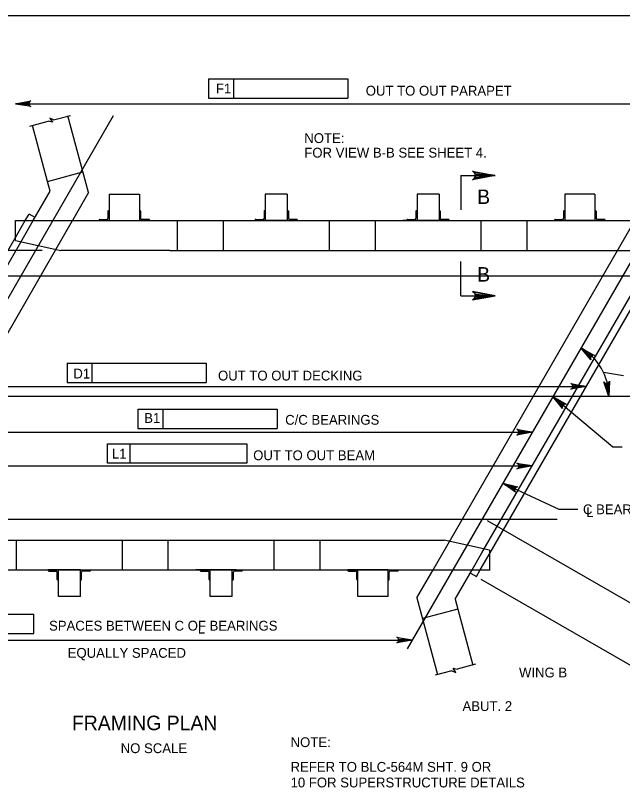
# Model space of a CAD drawing. Extents: x 638175 to 640495, y 294277 to 298435.
# Drawn here: x 638659.6 to 638845, y 295214.5 to 295450.5 of the extents above; entities that cross this region are included whole.
import ezdxf

# ---------------------------------------------------------------- set-up
doc = ezdxf.new("R2010")
doc.units = 0
for name, color, linetype in [('2', 7, 'Continuous'), ('3', 7, 'Continuous'), ('4', 7, 'Continuous')]:
    doc.layers.add(name, color=color, linetype=linetype)

msp = doc.modelspace()

# ---------------------------------------------------------------- linework, layer by layer
at = {"layer": '2'}
for p, q in [((638475.46, 295450.46), (639261.46, 295450.46)), ((638681.87, 295396.3), (638675.59, 295419.73)), ((638669.38, 295399.76), (638664.8, 295416.84)), ((638669.38, 295399.76), (638680.17, 295402.65)), ((638670.19, 295396.73), (638669.38, 295399.76)), ((638795.64, 295401.55), (638795.64, 295391.07)), ((638795.64, 295401.55), (638806.12, 295401.55)), ((638665, 295387.76), (638670.19, 295396.73)), ((638681.87, 295396.3), (638676.94, 295387.76)), ((638688.19, 295395.84), (638697.43, 295395.84)), ((638688.19, 295395.84), (638688.19, 295387.75)), ((638697.43, 295395.84), (638697.43, 295387.75)), ((638742.58, 295395.84), (638735.85, 295395.84)), ((638742.58, 295395.84), (638735.85, 295395.84)), ((638735.85, 295395.84), (638735.85, 295387.75)), ((638742.58, 295395.84), (638742.58, 295387.75)), ((638788.95, 295395.84), (638782.22, 295395.84)), ((638788.95, 295395.84), (638782.22, 295395.84)), ((638788.95, 295395.84), (638782.22, 295395.84)), ((638782.22, 295395.84), (638782.22, 295387.75)), ((638788.95, 295395.84), (638788.95, 295387.75)), ((638836.56, 295395.84), (638827.33, 295395.84)), ((638827.33, 295395.84), (638827.33, 295387.75)), ((638836.56, 295395.84), (638836.56, 295387.75)), ((638687.83, 295390.66), (638687.83, 295388.48)), ((638688.01, 295390.84), (638688.19, 295390.84)), ((638688.19, 295390.84), (638688.19, 295387.75)), ((638697.61, 295390.84), (638697.43, 295390.84)), ((638697.43, 295390.84), (638697.43, 295387.75)), ((638697.79, 295390.66), (638697.79, 295388.48)), ((638735.49, 295390.66), (638735.49, 295388.48)), ((638735.67, 295390.84), (638735.85, 295390.84)), ((638735.85, 295390.84), (638735.85, 295387.75)), ((638742.76, 295390.84), (638742.58, 295390.84)), ((638742.58, 295390.84), (638742.58, 295387.75)), ((638742.95, 295390.66), (638742.95, 295388.48)), ((638781.85, 295390.66), (638781.85, 295388.48)), ((638782.04, 295390.84), (638782.22, 295390.84)), ((638782.22, 295390.84), (638782.22, 295387.75)), ((638789.13, 295390.84), (638788.95, 295390.84)), ((638788.95, 295390.84), (638788.95, 295387.75)), ((638789.31, 295390.66), (638789.31, 295388.48)), ((638826.96, 295390.66), (638826.96, 295388.48)), ((638827.15, 295390.84), (638827.33, 295390.84)), ((638827.33, 295390.84), (638827.33, 295387.75)), ((638836.75, 295390.84), (638836.56, 295390.84)), ((638836.56, 295390.84), (638836.56, 295387.75)), ((638836.93, 295390.66), (638836.93, 295388.48)), ((638615.32, 295281.03), (638676.94, 295387.76)), ((638659.57, 295387.75), (638863.14, 295387.75)), ((638659.57, 295382.59), (638662.55, 295387.75)), ((638659.57, 295381.72), (638659.57, 295387.75)), ((638662.02, 295382.59), (638665, 295387.76)), ((638662.55, 295387.75), (638663.71, 295389.77)), ((638665.56, 295388.71), (638663.71, 295389.77)), ((638665, 295387.76), (638860.69, 295387.76)), ((638685.1, 295387.94), (638685.1, 295387.75)), ((638688.19, 295387.75), (638685.1, 295387.75)), ((638685.28, 295388.12), (638687.46, 295388.12)), ((638688.19, 295387.75), (638697.43, 295387.75)), ((638697.43, 295387.75), (638700.52, 295387.75)), ((638700.34, 295388.12), (638698.15, 295388.12)), ((638700.52, 295387.94), (638700.52, 295387.75)), ((638708.98, 295387.75), (638708.98, 295378.63)), ((638723.05, 295387.75), (638723.05, 295378.63)), ((638732.76, 295387.94), (638732.76, 295387.75)), ((638735.85, 295387.75), (638732.76, 295387.75)), ((638732.95, 295388.12), (638735.13, 295388.12)), ((638742.58, 295387.75), (638735.85, 295387.75)), ((638742.58, 295387.75), (638735.85, 295387.75)), ((638742.58, 295387.75), (638745.67, 295387.75)), ((638745.49, 295388.12), (638743.31, 295388.12)), ((638745.67, 295387.94), (638745.67, 295387.75)), ((638755.39, 295387.75), (638755.39, 295378.63)), ((638769.41, 295387.75), (638769.41, 295378.63)), ((638780.96, 295387.75), (638777.87, 295387.75)), ((638779.13, 295387.94), (638779.13, 295387.75)), ((638782.22, 295387.75), (638779.13, 295387.75)), ((638779.31, 295388.12), (638781.49, 295388.12)), ((638790.2, 295387.75), (638780.96, 295387.75)), ((638788.95, 295387.75), (638782.22, 295387.75)), ((638788.95, 295387.75), (638782.22, 295387.75)), ((638787.14, 295281.03), (638848.76, 295387.76)), ((638788.95, 295387.75), (638792.04, 295387.75)), ((638791.85, 295388.12), (638789.67, 295388.12)), ((638790.2, 295387.75), (638793.29, 295387.75)), ((638792.04, 295387.94), (638792.04, 295387.75)), ((638801.75, 295387.75), (638801.75, 295378.63)), ((638815.78, 295387.75), (638815.78, 295378.63)), ((638824.24, 295387.94), (638824.24, 295387.75)), ((638827.33, 295387.75), (638824.24, 295387.75)), ((638824.42, 295388.12), (638826.6, 295388.12)), ((638836.56, 295387.75), (638827.33, 295387.75)), ((638836.56, 295387.75), (638839.65, 295387.75)), ((638839.47, 295388.12), (638837.29, 295388.12)), ((638839.65, 295387.94), (638839.65, 295387.75)), ((638604.93, 295287.95), (638659.57, 295382.59)), ((638606.97, 295287.25), (638662.02, 295382.59)), ((638659.57, 295381.72), (638673.41, 295378.63)), ((638802.05, 295286.2), (638857.1, 295381.54)), ((638804.51, 295286.2), (638859.56, 295381.54)), ((638706.72, 295378.63), (638673.41, 295378.63)), ((638706.72, 295378.63), (638849.29, 295378.63)), ((638795.64, 295364.82), (638795.64, 295375.31)), ((638795.64, 295364.82), (638806.12, 295364.82)), ((638648.08, 295290.15), (638790.52, 295290.15)), ((638659.88, 295281.03), (638659.88, 295290.15)), ((638692.22, 295281.03), (638692.22, 295290.15)), ((638706.24, 295281.03), (638706.24, 295290.15)), ((638738.58, 295281.03), (638738.58, 295290.15)), ((638752.61, 295281.03), (638752.61, 295290.15)), ((638804.39, 295287.05), (638790.52, 295290.15)), ((638799.07, 295281.03), (638802.05, 295286.2)), ((638801.53, 295281.03), (638804.51, 295286.2)), ((638804.39, 295287.05), (638804.39, 295281.03)), ((638600.93, 295281.03), (638804.51, 295281.03)), ((638600.93, 295281.03), (638799.6, 295281.03)), ((638603.38, 295281.03), (638802.05, 295281.03)), ((638669.59, 295280.84), (638669.59, 295281.03)), ((638672.69, 295281.03), (638669.59, 295281.03)), ((638669.78, 295280.66), (638671.96, 295280.66)), ((638672.32, 295278.12), (638672.32, 295280.3)), ((638679.41, 295281.03), (638672.69, 295281.03)), ((638679.41, 295281.03), (638672.69, 295281.03)), ((638672.69, 295277.94), (638672.69, 295281.03)), ((638672.69, 295272.94), (638672.69, 295281.03)), ((638679.41, 295281.03), (638682.5, 295281.03)), ((638679.41, 295277.94), (638679.41, 295281.03)), ((638679.41, 295272.94), (638679.41, 295281.03)), ((638679.78, 295278.12), (638679.78, 295280.3)), ((638682.32, 295280.66), (638680.14, 295280.66)), ((638682.5, 295280.84), (638682.5, 295281.03)), ((638717.79, 295281.03), (638714.7, 295281.03)), ((638715.96, 295280.84), (638715.96, 295281.03)), ((638719.05, 295281.03), (638715.96, 295281.03)), ((638716.14, 295280.66), (638718.32, 295280.66)), ((638727.03, 295281.03), (638717.79, 295281.03)), ((638718.69, 295278.12), (638718.69, 295280.3)), ((638725.78, 295281.03), (638719.05, 295281.03)), ((638725.78, 295281.03), (638719.05, 295281.03)), ((638719.05, 295277.94), (638719.05, 295281.03)), ((638719.05, 295272.94), (638719.05, 295281.03)), ((638725.78, 295281.03), (638728.87, 295281.03)), ((638725.78, 295277.94), (638725.78, 295281.03)), ((638725.78, 295272.94), (638725.78, 295281.03)), ((638726.14, 295278.12), (638726.14, 295280.3)), ((638728.69, 295280.66), (638726.5, 295280.66)), ((638727.03, 295281.03), (638730.12, 295281.03)), ((638728.87, 295280.84), (638728.87, 295281.03)), ((638761.07, 295280.84), (638761.07, 295281.03)), ((638764.16, 295281.03), (638761.07, 295281.03)), ((638761.25, 295280.66), (638763.43, 295280.66)), ((638763.79, 295278.12), (638763.79, 295280.3)), ((638773.39, 295281.03), (638764.16, 295281.03)), ((638764.16, 295272.94), (638764.16, 295281.03)), ((638764.16, 295277.94), (638764.16, 295281.03)), ((638773.39, 295281.03), (638776.49, 295281.03)), ((638773.39, 295272.94), (638773.39, 295281.03)), ((638773.39, 295277.94), (638773.39, 295281.03)), ((638773.76, 295278.12), (638773.76, 295280.3)), ((638776.3, 295280.66), (638774.12, 295280.66)), ((638776.49, 295280.84), (638776.49, 295281.03)), ((638782.2, 295272.48), (638787.14, 295281.03)), ((638793.89, 295272.05), (638799.07, 295281.03)), ((638798.52, 295280.07), (638800.36, 295279.01)), ((638800.36, 295279.01), (638801.53, 295281.03)), ((638672.5, 295277.94), (638672.69, 295277.94)), ((638679.59, 295277.94), (638679.41, 295277.94)), ((638718.87, 295277.94), (638719.05, 295277.94)), ((638725.96, 295277.94), (638725.78, 295277.94)), ((638763.98, 295277.94), (638764.16, 295277.94)), ((638773.58, 295277.94), (638773.39, 295277.94)), ((638679.41, 295272.94), (638672.69, 295272.94)), ((638679.41, 295272.94), (638672.69, 295272.94)), ((638725.78, 295272.94), (638719.05, 295272.94)), ((638725.78, 295272.94), (638719.05, 295272.94)), ((638725.78, 295272.94), (638719.05, 295272.94)), ((638773.39, 295272.94), (638764.16, 295272.94)), ((638782.2, 295272.48), (638788.48, 295249.06)), ((638793.89, 295272.05), (638794.7, 295269.03)), ((638638.68, 295267.51), (638665.18, 295267.51)), ((638665.18, 295261.6), (638665.18, 295267.51)), ((638794.7, 295269.03), (638783.91, 295266.13)), ((638794.7, 295269.03), (638799.27, 295251.95)), ((638638.67, 295261.6), (638665.18, 295261.6))]:
    msp.add_line(p, q, dxfattribs=at)
for points in [[(638806.12, 295401.55), (638799.13, 295400.24), (638799.67, 295400.62), (638799.95, 295401.08), (638800.03, 295401.55), (638799.95, 295402.02), (638799.67, 295402.49), (638799.13, 295402.86), (638806.12, 295401.55), (638799.67, 295402.49), (638799.95, 295402.02), (638806.12, 295401.55), (638800.03, 295401.55), (638799.95, 295401.08), (638806.12, 295401.55), (638799.67, 295400.62)], [(638806.12, 295364.82), (638799.13, 295366.13), (638799.67, 295365.76), (638799.95, 295365.29), (638800.03, 295364.82), (638799.95, 295364.35), (638799.67, 295363.89), (638799.13, 295363.51), (638806.12, 295364.82), (638799.67, 295363.89), (638799.95, 295364.35), (638806.12, 295364.82), (638800.03, 295364.82), (638799.95, 295365.29), (638806.12, 295364.82), (638799.67, 295365.76)]]:
    msp.add_lwpolyline(points, dxfattribs=at)
for centre, radius, start, end in [((638688.01, 295390.66), 0.182, 90, 179.9984), ((638697.61, 295390.66), 0.182, 0.0016, 90), ((638735.67, 295390.66), 0.182, 90, 179.9984), ((638742.76, 295390.66), 0.182, 0.0016, 90), ((638782.04, 295390.66), 0.182, 90, 179.9984), ((638789.13, 295390.66), 0.182, 0.0016, 90), ((638827.15, 295390.66), 0.182, 90, 179.9984), ((638836.75, 295390.66), 0.182, 0.0016, 90), ((638685.28, 295387.94), 0.182, 90, 179.9984), ((638687.46, 295388.48), 0.364, 270, 359.9984), ((638698.15, 295388.48), 0.364, 180.0016, 270), ((638700.34, 295387.94), 0.182, 0.0016, 90), ((638732.95, 295387.94), 0.182, 90, 179.9984), ((638735.13, 295388.48), 0.364, 270, 359.9984), ((638743.31, 295388.48), 0.364, 180.0016, 270), ((638745.49, 295387.94), 0.182, 0.0016, 90), ((638779.31, 295387.94), 0.182, 90, 179.9984), ((638781.49, 295388.48), 0.364, 270, 359.9984), ((638789.67, 295388.48), 0.364, 180.0016, 270), ((638791.85, 295387.94), 0.182, 0.0016, 90), ((638824.42, 295387.94), 0.182, 90, 179.9984), ((638826.6, 295388.48), 0.364, 270, 359.9984), ((638837.29, 295388.48), 0.364, 180.0016, 270), ((638839.47, 295387.94), 0.182, 0.0016, 90), ((638669.78, 295280.84), 0.182, 180.0016, 270), ((638671.96, 295280.3), 0.364, 0.0016, 90), ((638680.14, 295280.3), 0.364, 90, 179.9984), ((638682.32, 295280.84), 0.182, 270, 359.9984), ((638716.14, 295280.84), 0.182, 180.0016, 270), ((638718.32, 295280.3), 0.364, 0.0016, 90), ((638726.5, 295280.3), 0.364, 90, 179.9984), ((638728.69, 295280.84), 0.182, 270, 359.9984), ((638761.25, 295280.84), 0.182, 180.0016, 270), ((638763.43, 295280.3), 0.364, 0.0016, 90), ((638774.12, 295280.3), 0.364, 90, 179.9984), ((638776.3, 295280.84), 0.182, 270, 359.9984), ((638672.5, 295278.12), 0.182, 180.0016, 270), ((638679.59, 295278.12), 0.182, 270, 359.9984), ((638718.87, 295278.12), 0.182, 180.0016, 270), ((638725.96, 295278.12), 0.182, 270, 359.9984), ((638763.98, 295278.12), 0.182, 180.0016, 270), ((638773.58, 295278.12), 0.182, 270, 359.9984)]:
    msp.add_arc(centre, radius, start, end, dxfattribs=at)
at = {"layer": '3'}
for p, q in [((638671.23, 295418.56), (638670.03, 295419.08)), ((638670.03, 295419.08), (638670.85, 295417.83)), ((638671.23, 295418.56), (638676.36, 295419.93)), ((638663.96, 295416.61), (638669.56, 295418.11)), ((638670.85, 295417.83), (638669.56, 295418.11)), ((638793.22, 295250.96), (638794.51, 295250.67)), ((638794.05, 295249.71), (638793.22, 295250.96)), ((638800.11, 295252.17), (638794.51, 295250.67)), ((638792.84, 295250.22), (638787.72, 295248.85)), ((638792.84, 295250.22), (638794.05, 295249.71))]:
    msp.add_line(p, q, dxfattribs=at)
at = {"layer": '4'}
for p, q in [((638718.57, 295431.06), (638761.09, 295431.06)), ((638718.57, 295431.06), (638718.57, 295425.15)), ((638726.13, 295431.06), (638726.13, 295425.15)), ((638761.09, 295431.06), (638761.09, 295425.15)), ((638659.57, 295423.47), (638863.14, 295423.47)), ((638718.57, 295425.15), (638761.09, 295425.15)), ((638689.46, 295419.78), (638595.44, 295256.93)), ((638873.21, 295419.78), (638779.19, 295256.93)), ((638667.7, 295378.63), (638501.09, 295378.63)), ((638863.78, 295370.8), (638515.73, 295370.8)), ((638675.34, 295344.19), (638717.86, 295344.19)), ((638675.34, 295344.19), (638675.34, 295338.28)), ((638682.9, 295344.19), (638682.9, 295338.28)), ((638717.86, 295344.19), (638717.86, 295338.28)), ((638839.13, 295341.47), (638845.27, 295340.44)), ((638675.34, 295338.28), (638717.86, 295338.28)), ((638633.3, 295337.09), (638833.89, 295337.09)), ((638882.76, 295333.98), (638590.47, 295333.98)), ((638823.67, 295333.97), (638842.03, 295318.63)), ((638696.99, 295330.16), (638739.51, 295330.16)), ((638696.99, 295330.16), (638696.99, 295324.26)), ((638704.55, 295330.16), (638704.55, 295324.26)), ((638739.51, 295330.16), (638739.51, 295324.26)), ((638696.99, 295324.26), (638739.51, 295324.26)), ((638633.64, 295323.11), (638817.4, 295323.11)), ((638687.7, 295319.52), (638730.22, 295319.52)), ((638687.7, 295313.61), (638687.7, 295319.52)), ((638694.59, 295313.61), (638694.59, 295319.52)), ((638730.22, 295319.52), (638730.22, 295313.61)), ((638842.03, 295318.63), (638844.87, 295318.63)), ((638621.72, 295312.78), (638817.4, 295312.78)), ((638730.22, 295313.61), (638687.7, 295313.61)), ((638808.38, 295307.49), (638825.58, 295299.6)), ((638825.58, 295299.6), (638831.33, 295299.6)), ((638825.02, 295296.45), (638515.26, 295296.45)), ((638803.69, 295296.11), (638881.52, 295251.18)), ((638801.71, 295278.23), (638908.35, 295216.66)), ((638596.97, 295259.58), (638780.72, 295259.58)), ((638600.15, 295259.58), (638777.9, 295259.58))]:
    msp.add_line(p, q, dxfattribs=at)
for points in [[(638659.57, 295423.47), (638664.23, 295424.35), (638663.87, 295424.1), (638663.68, 295423.79), (638663.63, 295423.47), (638663.68, 295423.16), (638663.87, 295422.85), (638664.23, 295422.6), (638659.57, 295423.47), (638663.87, 295422.85), (638663.68, 295423.16), (638659.57, 295423.47), (638663.63, 295423.47), (638663.68, 295423.79), (638659.57, 295423.47), (638663.87, 295424.1)], [(638832.27, 295348.85), (638836.43, 295346.57), (638835.99, 295346.6), (638835.65, 295346.48), (638835.41, 295346.27), (638835.26, 295346), (638835.2, 295345.64), (638835.32, 295345.22), (638832.27, 295348.85), (638835.2, 295345.64), (638835.26, 295346), (638832.27, 295348.85), (638835.41, 295346.27), (638835.65, 295346.48), (638832.27, 295348.85), (638835.99, 295346.6)], [(638840.85, 295333.99), (638839.25, 295338.45), (638839.55, 295338.14), (638839.89, 295338), (638840.21, 295338), (638840.51, 295338.1), (638840.79, 295338.33), (638840.98, 295338.73), (638840.85, 295333.99), (638840.79, 295338.33), (638840.51, 295338.1), (638840.85, 295333.99), (638840.21, 295338), (638839.89, 295338), (638840.85, 295333.99), (638839.55, 295338.14)], [(638833.89, 295337.09), (638829.23, 295336.21), (638829.59, 295336.46), (638829.78, 295336.77), (638829.83, 295337.09), (638829.78, 295337.4), (638829.59, 295337.71), (638829.23, 295337.96), (638833.89, 295337.09), (638829.59, 295337.71), (638829.78, 295337.4), (638833.89, 295337.09), (638829.83, 295337.09), (638829.78, 295336.77), (638833.89, 295337.09), (638829.59, 295336.46)], [(638823.67, 295333.97), (638827.81, 295331.66), (638827.37, 295331.7), (638827.03, 295331.57), (638826.79, 295331.37), (638826.63, 295331.1), (638826.57, 295330.74), (638826.69, 295330.32), (638823.67, 295333.97), (638826.57, 295330.74), (638826.63, 295331.1), (638823.67, 295333.97), (638826.79, 295331.37), (638827.03, 295331.57), (638823.67, 295333.97), (638827.37, 295331.7)], [(638817.4, 295323.11), (638812.74, 295322.23), (638813.09, 295322.48), (638813.28, 295322.79), (638813.33, 295323.11), (638813.28, 295323.42), (638813.09, 295323.73), (638812.74, 295323.98), (638817.4, 295323.11), (638813.09, 295323.73), (638813.28, 295323.42), (638817.4, 295323.11), (638813.33, 295323.11), (638813.28, 295322.79), (638817.4, 295323.11), (638813.09, 295322.48)], [(638817.4, 295312.78), (638812.74, 295311.91), (638813.1, 295312.15), (638813.28, 295312.47), (638813.34, 295312.78), (638813.28, 295313.09), (638813.1, 295313.4), (638812.74, 295313.65), (638817.4, 295312.78), (638813.1, 295313.4), (638813.28, 295313.09), (638817.4, 295312.78), (638813.34, 295312.78), (638813.28, 295312.47), (638817.4, 295312.78), (638813.1, 295312.15)], [(638808.38, 295307.49), (638812.99, 295306.37), (638812.56, 295306.29), (638812.26, 295306.08), (638812.08, 295305.82), (638812.01, 295305.51), (638812.05, 295305.16), (638812.27, 295304.78), (638808.38, 295307.49), (638812.05, 295305.16), (638812.01, 295305.51), (638808.38, 295307.49), (638812.08, 295305.82), (638812.26, 295306.08), (638808.38, 295307.49), (638812.56, 295306.29)], [(638780.72, 295259.58), (638776.06, 295258.71), (638776.42, 295258.96), (638776.61, 295259.27), (638776.66, 295259.58), (638776.61, 295259.9), (638776.42, 295260.21), (638776.06, 295260.46), (638780.72, 295259.58), (638776.42, 295260.21), (638776.61, 295259.9), (638780.72, 295259.58), (638776.66, 295259.58), (638776.61, 295259.27), (638780.72, 295259.58), (638776.42, 295258.96)]]:
    msp.add_lwpolyline(points, dxfattribs=at)
msp.add_arc((638823.67, 295333.98), 17.18, 0.0029, 59.9982, dxfattribs=at)

# ---------------------------------------------------------------- texts
at = {"layer": '2'}
for s, p in [('SPACES BETWEEN C OF BEARINGS', (638669.82, 295262.47)), ('L', (638715.26, 295261.56)), ('EQUALLY SPACED', (638675.52, 295254.16))]:
    msp.add_text(s, height=3, dxfattribs=at).set_placement(p)
at = {"layer": '4'}
for s, height, rotation, p in [('F1', 3, 359.9382, (638720.78, 295426.61)), ('B', 4.43, 360, (638800.58, 295392.83)), ('D1', 3, 359.9382, (638677.25, 295339.51)), ('B1', 3, 359.9382, (638698.89, 295325.94))]:
    msp.add_text(s, height=height, rotation=rotation, dxfattribs=at).set_placement(p)
for s, height, p in [('OUT TO OUT PARAPET ', 3, (638766.56, 295425.95)), ('NOTE:', 3, (638747.79, 295411.46)), ('FOR VIEW B-B SEE SHEET 4.', 3, (638747.79, 295407.02)), ('B', 4.43, (638800.58, 295369.12)), ('OUT TO OUT DECKING', 3, (638721.43, 295338.9)), ('C/C BEARINGS', 3, (638741.95, 295325.38)), ('L1', 3, (638689.02, 295315.04)), ('OUT TO OUT BEAM', 3, (638732.18, 295314.55)), ('C BEARINGS', 3, (638832.91, 295298.03)), ('L', 3, (638833.9, 295297.18)), ('WING B', 3, (638813.37, 295248.16)), ('ABUT. 2', 3, (638796.11, 295237.9)), ('FRAMING PLAN', 4.4292, (638676.81, 295232.04)), ('NOTE:', 3, (638743.6, 295226.87)), ('NO SCALE', 3, (638691.71, 295225.03)), ('REFER TO BLC-564M SHT. 9 OR', 3, (638743.6, 295219.33)), ('10 FOR SUPERSTRUCTURE DETAILS', 3, (638743.6, 295214.55))]:
    msp.add_text(s, height=height, dxfattribs=at).set_placement(p)

doc.saveas('drawing.dxf')
